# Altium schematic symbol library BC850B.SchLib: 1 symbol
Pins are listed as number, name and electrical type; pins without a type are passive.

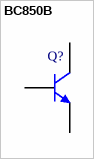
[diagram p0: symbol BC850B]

## BC850B
designator Q?
NPN Silicon AF Transistor, 45 V VCEO, 100 mA IC, SOT23, Reel, Green; Manufacturer: Infineon; PartNumber: BC850B; F (typ): 1.2 dB; fT (typ): 250 MHz; Green: TRUE; IC: 2 mA; IC (max): 100 mA; ICBO (max): 15 nA; ICM (max): 200 mA; VCBO (max): 50 V; VCE: 5 V; VCEO (max): 45 V; VEBO (max): 6 V
footprint INF-SOT23_N (SOT23, 3-Leads, Body 2.9x1.3 mm, Pitch 0.95 mm, IPC Medium Density)
footprint INF-SOT23_L (SOT23, 3-Leads, Body 2.9x1.3 mm, Pitch 0.95 mm, IPC High Density)
footprint INF-SOT23_M (SOT23, 3-Leads, Body 2.9x1.3 mm, Pitch 0.95 mm, IPC Low Density)
pins: 1 B, 2 E, 3 C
